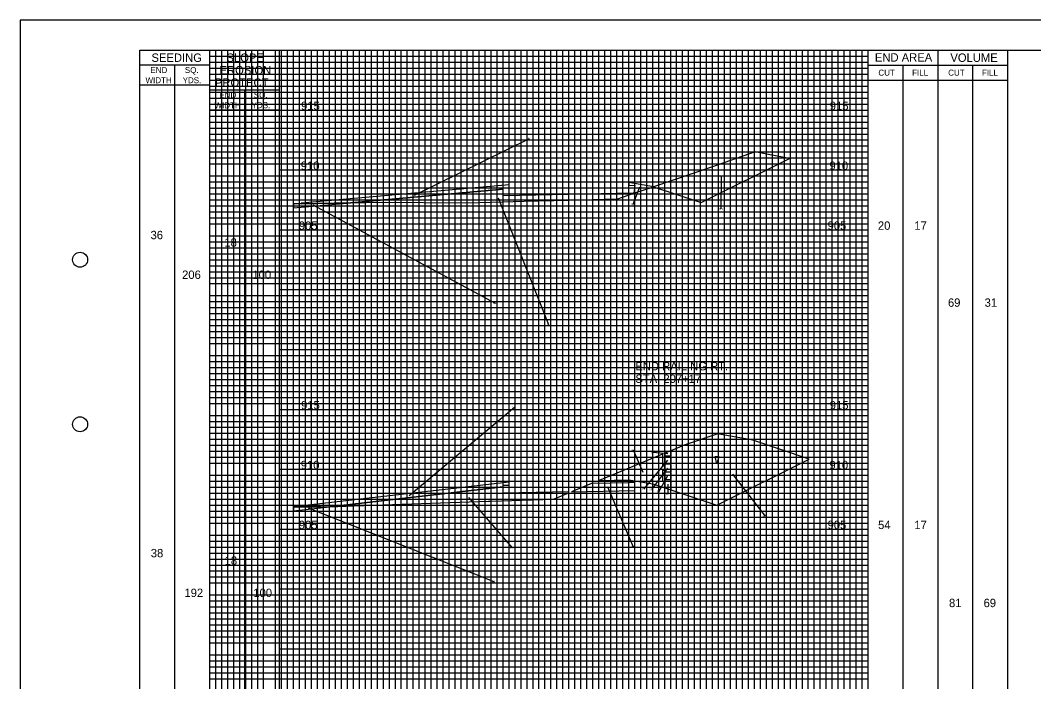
# Model space of a CAD drawing. Extents: x -73 to 160, y -2 to 1877.
# Drawn here: x -10 to 74.7, y 1547.2 to 1602.5 of the extents above; entities that cross this region are included whole.
import ezdxf

# ---------------------------------------------------------------- set-up
doc = ezdxf.new("R2010")
doc.units = 0
for name, color, linetype in [('DR_P_Flood_Boundary', 7, 'Continuous'), ('GK_Cells', 7, 'Continuous'), ('RD_X_Fence', 7, 'Continuous'), ('TX_X_5', 7, 'Continuous'), ('UT_P_Water_Cells', 7, 'Continuous'), ('XS_P_Pavt_Surface', 7, 'Continuous'), ('XS_X_Ground_Line', 7, 'Continuous')]:
    doc.layers.add(name, color=color, linetype=linetype)

msp = doc.modelspace()

# ---------------------------------------------------------------- linework, layer by layer
at = {"layer": 'DR_P_Flood_Boundary'}
for p, q in [((15.832, 1495), (15.832, 1600)), ((20.832, 1495), (20.832, 1600)), ((25.832, 1495), (25.832, 1600)), ((30.832, 1495), (30.832, 1600)), ((35.832, 1495), (35.832, 1600)), ((40.832, 1495), (40.832, 1600)), ((45.832, 1495), (45.832, 1600)), ((50.832, 1495), (50.832, 1600)), ((55.832, 1495), (55.832, 1600)), ((5.832, 1595), (60.832, 1595)), ((11.665, 1590), (60.832, 1590)), ((11.665, 1585), (60.832, 1585)), ((11.665, 1580), (60.832, 1580)), ((11.665, 1575), (60.832, 1575)), ((11.665, 1570), (60.832, 1570)), ((11.665, 1565), (60.832, 1565)), ((11.665, 1560), (60.832, 1560)), ((11.665, 1555), (60.832, 1555)), ((11.665, 1550), (60.832, 1550))]:
    msp.add_line(p, q, dxfattribs=at)
at = {"layer": 'GK_Cells'}
msp.add_lwpolyline([(0, 1600), (157.5, 1600), (157.5, 1495), (0, 1495)], close=True, dxfattribs=at)
for centre in [(-5, 1582.5), (-5, 1568.75)]:
    msp.add_circle(centre, 0.625, dxfattribs=at)
at = {"layer": 'RD_X_Fence'}
for p, q in [((22.926, 1587.9), (32.526, 1592.622)), ((46.887, 1587.271), (54.269, 1590.962)), ((48.543, 1589.429), (48.514, 1586.74)), ((30.832, 1588.756), (13.453, 1587.215)), ((30.332, 1588.382), (17.617, 1587.255)), ((17.617, 1587.255), (30.332, 1588.382)), ((30.332, 1588.496), (30.832, 1588.506)), ((30.332, 1588.382), (30.332, 1588.496)), ((30.332, 1587.83), (30.332, 1588.382)), ((42.903, 1588.6), (40.832, 1588.956)), ((40.832, 1588.706), (41.332, 1588.716)), ((41.734, 1588.547), (41.176, 1587.101)), ((41.332, 1588.716), (41.266, 1588.048)), ((41.266, 1588.048), (42.903, 1588.6)), ((42.903, 1588.6), (46.887, 1587.271)), ((29.915, 1587.67), (34.129, 1577.084)), ((41.266, 1588.048), (30.332, 1587.83)), ((32.089, 1587.379), (35.833, 1587.482)), ((12.832, 1586.83), (17.617, 1587.255)), ((12.832, 1587.16), (12.832, 1586.83)), ((13.456, 1587.174), (17.617, 1587.255)), ((14.428, 1587.082), (29.683, 1578.883)), ((29.332, 1587.304), (32.089, 1587.379)), ((22.482, 1562.804), (31.277, 1570.192)), ((48.199, 1567.936), (45.462, 1567.016)), ((48.254, 1567.954), (48.199, 1567.936)), ((51.194, 1567.436), (48.254, 1567.954)), ((55.903, 1565.853), (51.194, 1567.436)), ((43.66, 1566.269), (38.365, 1564.072)), ((42.046, 1564.719), (41.215, 1566.586)), ((42.046, 1564.719), (41.215, 1566.586)), ((42.046, 1564.719), (41.215, 1566.586)), ((44.108, 1566.282), (42.835, 1566.384)), ((44.108, 1566.282), (42.835, 1566.384)), ((43.666, 1566.109), (43.666, 1566.253)), ((44.332, 1566.548), (43.832, 1566.34)), ((45.462, 1567.016), (44.332, 1566.548)), ((44.332, 1566.114), (44.332, 1566.548)), ((44.332, 1566.548), (44.332, 1566.114)), ((44.08, 1565.76), (42.094, 1563.359)), ((43.666, 1566.107), (43.625, 1566.109)), ((43.666, 1565.437), (43.625, 1565.439)), ((43.625, 1565.439), (43.666, 1565.439)), ((43.666, 1565.439), (43.666, 1566.107)), ((43.666, 1565.253), (43.666, 1565.437)), ((43.832, 1566.107), (44.332, 1566.109)), ((44.332, 1566.067), (43.832, 1566.097)), ((43.832, 1566.097), (43.832, 1565.437)), ((43.832, 1565.437), (44.332, 1565.439)), ((44.332, 1565.397), (43.832, 1565.427)), ((44.332, 1566.062), (44.332, 1565.444)), ((44.332, 1564.784), (44.332, 1565.392)), ((44.332, 1565.392), (44.332, 1564.784)), ((48.197, 1565.463), (48.037, 1566.063)), ((48.359, 1566.063), (48.197, 1565.463)), ((48.197, 1562), (55.903, 1565.853)), ((44.08, 1565.095), (42.718, 1563.31)), ((43.666, 1564.777), (43.625, 1564.779)), ((43.832, 1565.253), (43.666, 1565.253)), ((43.666, 1564.779), (43.666, 1564.923)), ((43.666, 1564.923), (43.832, 1564.923)), ((43.666, 1564.151), (43.666, 1564.777)), ((43.832, 1564.923), (43.832, 1565.253)), ((43.832, 1564.777), (44.332, 1564.779)), ((44.332, 1564.737), (43.832, 1564.767)), ((43.832, 1564.767), (43.832, 1564.151)), ((44.332, 1564.156), (44.332, 1564.732)), ((44.332, 1564.732), (44.332, 1564.156)), ((49.489, 1564.589), (52.234, 1561.085)), ((30.832, 1563.922), (12.832, 1561.855)), ((30.832, 1563.817), (30.832, 1563.922)), ((30.832, 1563.672), (30.832, 1563.817)), ((37.731, 1563.81), (36.043, 1563.109)), ((38.365, 1564.072), (40.832, 1564.122)), ((40.832, 1564.122), (42.832, 1563.788)), ((41.332, 1563.215), (41.332, 1563.882)), ((42.832, 1563.788), (43.832, 1563.455)), ((44.08, 1564.452), (43.333, 1563.134)), ((43.625, 1564.151), (43.666, 1564.151)), ((43.666, 1564.149), (43.625, 1564.151)), ((43.666, 1563.965), (43.666, 1564.149)), ((43.832, 1563.965), (43.666, 1563.965)), ((43.832, 1564.151), (44.332, 1564.151)), ((44.332, 1564.109), (43.832, 1564.139)), ((43.832, 1563.455), (43.832, 1563.965)), ((44.09, 1563.746), (44.084, 1562.91)), ((44.09, 1563.746), (44.084, 1562.91)), ((44.332, 1563.288), (44.332, 1564.104)), ((44.332, 1564.104), (44.332, 1563.288)), ((30.332, 1563.534), (15.831, 1561.87)), ((15.831, 1561.87), (30.332, 1563.534)), ((30.332, 1563.662), (30.832, 1563.672)), ((30.332, 1563.534), (30.332, 1563.662)), ((30.332, 1562.995), (30.332, 1563.534)), ((35.831, 1563.105), (30.332, 1562.995)), ((34.545, 1562.488), (35.832, 1563.022)), ((36.043, 1563.109), (41.332, 1563.215)), ((39.083, 1563.482), (41.204, 1558.511)), ((43.832, 1563.455), (44.332, 1563.288)), ((44.332, 1563.288), (48.197, 1562)), ((27.453, 1562.64), (31.093, 1558.429)), ((29.332, 1562.344), (34.545, 1562.488)), ((15.82, 1561.968), (12.832, 1561.855)), ((12.832, 1561.525), (15.831, 1561.87)), ((12.832, 1561.855), (12.832, 1561.525)), ((14.062, 1561.784), (29.564, 1555.622))]:
    msp.add_line(p, q, dxfattribs=at)
for points in [[(54.269, 1590.962), (52.631, 1591.248), (51.379, 1591.518), (47.755, 1590.234), (42.903, 1588.6)], [(30.832, 1588.506), (30.832, 1588.652), (30.832, 1588.756)], [(40.832, 1588.956), (40.832, 1588.852), (40.832, 1588.706)], [(35.833, 1587.482), (39.919, 1587.595), (41.266, 1588.048)], [(17.617, 1587.255), (13.456, 1587.174), (12.832, 1587.16)], [(13.453, 1587.215), (13.456, 1587.174)], [(17.617, 1587.255), (20.19, 1587.304), (27.19, 1587.245), (29.332, 1587.304)], [(43.666, 1566.253), (43.66, 1566.269)], [(43.832, 1566.34), (43.832, 1566.253), (43.832, 1566.107)], [(43.625, 1566.109), (43.666, 1566.109)], [(43.832, 1565.427), (43.832, 1565.253), (43.832, 1564.923), (43.832, 1564.777)], [(44.332, 1566.109), (44.332, 1566.114)], [(44.332, 1566.062), (44.332, 1566.067)], [(44.332, 1565.439), (44.332, 1565.444), (44.332, 1566.062)], [(44.332, 1565.392), (44.332, 1565.397)], [(48.037, 1566.063), (48.199, 1566.063), (48.359, 1566.063)], [(43.625, 1564.779), (43.666, 1564.779)], [(44.332, 1564.779), (44.332, 1564.784)], [(44.332, 1564.732), (44.332, 1564.737)], [(41.332, 1563.882), (40.832, 1563.872), (37.731, 1563.81)], [(43.832, 1564.139), (43.832, 1563.965), (43.832, 1563.455)], [(44.332, 1564.151), (44.332, 1564.156)], [(44.332, 1564.104), (44.332, 1564.109)], [(35.832, 1563.022), (35.831, 1563.105)], [(15.831, 1561.87), (17.904, 1561.95), (29.122, 1562.338), (29.332, 1562.344)], [(12.832, 1561.855), (14.061, 1561.861), (15.831, 1561.87)], [(15.831, 1561.87), (15.82, 1561.968)]]:
    msp.add_lwpolyline(points, dxfattribs=at)
for centre in [(44.318, 1566.088), (44.318, 1565.418), (44.318, 1564.758), (44.318, 1564.13)]:
    msp.add_arc(centre, 0.03, 299.86589, 60.13411, dxfattribs=at)
at = {"layer": 'TX_X_5'}
msp.add_lwpolyline([(-10, 1492.5), (160, 1492.5), (160, 1602.5), (-10, 1602.5)], close=True, dxfattribs=at)
at = {"layer": 'UT_P_Water_Cells'}
for p, q in [((5.832, 1599.5), (60.832, 1599.5)), ((6.332, 1495), (6.332, 1600)), ((6.832, 1495), (6.832, 1600)), ((7.332, 1495), (7.332, 1600)), ((7.832, 1495), (7.832, 1600)), ((8.332, 1495), (8.332, 1600)), ((8.832, 1495), (8.832, 1600)), ((9.332, 1495), (9.332, 1600)), ((9.832, 1495), (9.832, 1600)), ((10.332, 1495), (10.332, 1600)), ((11.332, 1495), (11.332, 1600)), ((11.832, 1495), (11.832, 1600)), ((12.332, 1495), (12.332, 1600)), ((12.832, 1495), (12.832, 1600)), ((13.332, 1495), (13.332, 1600)), ((13.832, 1495), (13.832, 1600)), ((14.332, 1495), (14.332, 1600)), ((14.832, 1495), (14.832, 1600)), ((15.332, 1495), (15.332, 1600)), ((16.332, 1495), (16.332, 1600)), ((16.832, 1495), (16.832, 1600)), ((17.332, 1495), (17.332, 1600)), ((17.832, 1495), (17.832, 1600)), ((18.332, 1495), (18.332, 1600)), ((18.832, 1495), (18.832, 1600)), ((19.332, 1495), (19.332, 1600)), ((19.832, 1495), (19.832, 1600)), ((20.332, 1495), (20.332, 1600)), ((21.332, 1495), (21.332, 1600)), ((21.832, 1495), (21.832, 1600)), ((22.332, 1495), (22.332, 1600)), ((22.832, 1495), (22.832, 1600)), ((23.332, 1495), (23.332, 1600)), ((23.832, 1495), (23.832, 1600)), ((24.332, 1495), (24.332, 1600)), ((24.832, 1495), (24.832, 1600)), ((25.332, 1495), (25.332, 1600)), ((26.332, 1495), (26.332, 1600)), ((26.832, 1495), (26.832, 1600)), ((27.332, 1495), (27.332, 1600)), ((27.832, 1495), (27.832, 1600)), ((28.332, 1495), (28.332, 1600)), ((28.832, 1495), (28.832, 1600)), ((29.332, 1495), (29.332, 1600)), ((29.832, 1495), (29.832, 1600)), ((30.332, 1495), (30.332, 1600)), ((31.332, 1495), (31.332, 1600)), ((31.832, 1495), (31.832, 1600)), ((32.332, 1495), (32.332, 1600)), ((32.832, 1495), (32.832, 1600)), ((33.332, 1495), (33.332, 1600)), ((33.832, 1495), (33.832, 1600)), ((34.332, 1495), (34.332, 1600)), ((34.832, 1495), (34.832, 1600)), ((35.332, 1495), (35.332, 1600)), ((36.332, 1495), (36.332, 1600)), ((36.832, 1495), (36.832, 1600)), ((37.332, 1495), (37.332, 1600)), ((37.832, 1495), (37.832, 1600)), ((38.332, 1495), (38.332, 1600)), ((38.832, 1495), (38.832, 1600)), ((39.332, 1495), (39.332, 1600)), ((39.832, 1495), (39.832, 1600)), ((40.332, 1495), (40.332, 1600)), ((41.332, 1495), (41.332, 1600)), ((41.832, 1495), (41.832, 1600)), ((42.332, 1495), (42.332, 1600)), ((42.832, 1495), (42.832, 1600)), ((43.332, 1495), (43.332, 1600)), ((43.832, 1495), (43.832, 1600)), ((44.332, 1495), (44.332, 1600)), ((44.832, 1495), (44.832, 1600)), ((45.332, 1495), (45.332, 1600)), ((46.332, 1495), (46.332, 1600)), ((46.832, 1495), (46.832, 1600)), ((47.332, 1495), (47.332, 1600)), ((47.832, 1495), (47.832, 1600)), ((48.332, 1495), (48.332, 1600)), ((48.832, 1495), (48.832, 1600)), ((49.332, 1495), (49.332, 1600)), ((49.832, 1495), (49.832, 1600)), ((50.332, 1495), (50.332, 1600)), ((51.332, 1495), (51.332, 1600)), ((51.832, 1495), (51.832, 1600)), ((52.332, 1495), (52.332, 1600)), ((52.832, 1495), (52.832, 1600)), ((53.332, 1495), (53.332, 1600)), ((53.832, 1495), (53.832, 1600)), ((54.332, 1495), (54.332, 1600)), ((54.832, 1495), (54.832, 1600)), ((55.332, 1495), (55.332, 1600)), ((56.332, 1495), (56.332, 1600)), ((56.832, 1495), (56.832, 1600)), ((57.332, 1495), (57.332, 1600)), ((57.832, 1495), (57.832, 1600)), ((58.332, 1495), (58.332, 1600)), ((58.832, 1495), (58.832, 1600)), ((59.332, 1495), (59.332, 1600)), ((59.832, 1495), (59.832, 1600)), ((60.332, 1495), (60.332, 1600)), ((5.832, 1599), (60.832, 1599)), ((5.832, 1598.5), (60.832, 1598.5)), ((5.832, 1598), (60.832, 1598)), ((5.832, 1597.5), (60.832, 1597.5)), ((5.832, 1597), (60.832, 1597)), ((5.832, 1596.5), (60.832, 1596.5)), ((5.832, 1596), (60.832, 1596)), ((5.832, 1595.5), (60.832, 1595.5)), ((5.832, 1594.5), (60.832, 1594.5)), ((5.832, 1594), (60.832, 1594)), ((5.832, 1593.5), (60.832, 1593.5)), ((5.832, 1593), (60.832, 1593)), ((5.832, 1592.5), (60.832, 1592.5)), ((5.832, 1592), (60.832, 1592)), ((5.832, 1591.5), (60.832, 1591.5)), ((5.832, 1591), (60.832, 1591)), ((5.832, 1590.5), (60.832, 1590.5)), ((5.832, 1589.5), (60.832, 1589.5)), ((5.832, 1589), (60.832, 1589)), ((5.832, 1588.5), (60.832, 1588.5)), ((5.832, 1588), (60.832, 1588)), ((5.832, 1587.5), (60.832, 1587.5)), ((5.832, 1587), (60.832, 1587)), ((5.832, 1586.5), (60.832, 1586.5)), ((5.832, 1586), (60.832, 1586)), ((5.832, 1585.5), (60.832, 1585.5)), ((5.832, 1584.5), (60.832, 1584.5)), ((5.832, 1584), (60.832, 1584)), ((5.832, 1583.5), (60.832, 1583.5)), ((5.832, 1583), (60.832, 1583)), ((5.832, 1582.5), (60.832, 1582.5)), ((5.832, 1582), (60.832, 1582)), ((5.832, 1581.5), (60.832, 1581.5)), ((5.832, 1581), (60.832, 1581)), ((5.832, 1580.5), (60.832, 1580.5)), ((5.832, 1579.5), (60.832, 1579.5)), ((5.832, 1579), (60.832, 1579)), ((5.832, 1578.5), (60.832, 1578.5)), ((5.832, 1578), (60.832, 1578)), ((5.832, 1577.5), (60.832, 1577.5)), ((5.832, 1577), (60.832, 1577)), ((5.832, 1576.5), (60.832, 1576.5)), ((5.832, 1576), (60.832, 1576)), ((5.832, 1575.5), (60.832, 1575.5)), ((5.832, 1574.5), (60.832, 1574.5)), ((5.832, 1574), (60.832, 1574)), ((5.832, 1573.5), (60.832, 1573.5)), ((5.832, 1573), (60.832, 1573)), ((5.832, 1572.5), (60.832, 1572.5)), ((5.832, 1572), (60.832, 1572)), ((5.832, 1571.5), (60.832, 1571.5)), ((5.832, 1571), (60.832, 1571)), ((5.832, 1570.5), (60.832, 1570.5)), ((5.832, 1569.5), (60.832, 1569.5)), ((5.832, 1569), (60.832, 1569)), ((5.832, 1568.5), (60.832, 1568.5)), ((5.832, 1568), (60.832, 1568)), ((5.832, 1567.5), (60.832, 1567.5)), ((5.832, 1567), (60.832, 1567)), ((5.832, 1566.5), (60.832, 1566.5)), ((5.832, 1566), (60.832, 1566)), ((5.832, 1565.5), (60.832, 1565.5)), ((5.832, 1564.5), (60.832, 1564.5)), ((5.832, 1564), (60.832, 1564)), ((5.832, 1563.5), (60.832, 1563.5)), ((5.832, 1563), (60.832, 1563)), ((5.832, 1562.5), (60.832, 1562.5)), ((5.832, 1562), (60.832, 1562)), ((5.832, 1561.5), (60.832, 1561.5)), ((5.832, 1561), (60.832, 1561)), ((5.832, 1560.5), (60.832, 1560.5)), ((5.832, 1559.5), (60.832, 1559.5)), ((5.832, 1559), (60.832, 1559)), ((5.832, 1558.5), (60.832, 1558.5)), ((5.832, 1558), (60.832, 1558)), ((5.832, 1557.5), (60.832, 1557.5)), ((5.832, 1557), (60.832, 1557)), ((5.832, 1556.5), (60.832, 1556.5)), ((5.832, 1556), (60.832, 1556)), ((5.832, 1555.5), (60.832, 1555.5)), ((5.832, 1554.5), (60.832, 1554.5)), ((5.832, 1554), (60.832, 1554)), ((5.832, 1553.5), (60.832, 1553.5)), ((5.832, 1553), (60.832, 1553)), ((5.832, 1552.5), (60.832, 1552.5)), ((5.832, 1552), (60.832, 1552)), ((5.832, 1551.5), (60.832, 1551.5)), ((5.832, 1551), (60.832, 1551)), ((5.832, 1550.5), (60.832, 1550.5)), ((5.832, 1549.5), (60.832, 1549.5)), ((5.832, 1549), (60.832, 1549)), ((5.832, 1548.5), (60.832, 1548.5)), ((5.832, 1548), (60.832, 1548)), ((5.832, 1547.5), (60.832, 1547.5))]:
    msp.add_line(p, q, dxfattribs=at)
at = {"layer": 'XS_X_Ground_Line'}
for p, q in [((5.832, 1495), (5.832, 1600)), ((5.832, 1495), (5.832, 1600)), ((11.665, 1495), (11.665, 1600)), ((60.832, 1495), (60.832, 1600)), ((66.667, 1495), (66.667, 1600)), ((72.5, 1495), (72.5, 1600)), ((5.832, 1598.75), (0, 1598.75)), ((2.916, 1495), (2.916, 1598.75)), ((60.832, 1598.75), (72.5, 1598.75)), ((63.75, 1495), (63.75, 1598.75)), ((69.583, 1495), (69.583, 1598.75)), ((5.832, 1597.083), (0, 1597.083)), ((60.832, 1597.5), (72.5, 1597.5)), ((11.665, 1596.667), (5.832, 1596.667)), ((8.749, 1495), (8.749, 1596.667)), ((11.665, 1595), (5.832, 1595))]:
    msp.add_line(p, q, dxfattribs=at)

# ---------------------------------------------------------------- texts
at = {"layer": 'RD_X_Fence'}
for s, p in [('5.1', (32.391, 1592.552)), ('0.8', (41.023, 1587.031)), ('18.6', (48.33, 1586.67)), ('0.8', (29.52, 1578.813)), ('11.6', (33.964, 1577.014)), ('5.4', (31.119, 1570.122)), ('6.5', (41.068, 1566.516)), ('0.2', (42.683, 1566.314)), ('0.3', (41.941, 1563.289)), ('0.3', (42.565, 1563.24)), ('0.3', (43.18, 1563.064)), ('0.4', (43.932, 1562.84)), ('42.0', (52.022, 1561.015)), ('11.3', (30.928, 1558.359)), ('3.0', (41.042, 1558.441)), ('0.6', (29.398, 1555.552))]:
    msp.add_text(s, height=0.14, dxfattribs=at).set_placement(p)
at = {"layer": 'XS_P_Pavt_Surface'}
for s, p in [('915', (13.458, 1595)), ('915', (57.625, 1595)), ('910', (13.43, 1590)), ('910', (57.598, 1590)), ('905', (13.27, 1585)), ('905', (57.438, 1585)), ('20', (61.644, 1585)), ('36', (0.885, 1584.212)), ('17', (64.689, 1585)), ('18', (7.052, 1583.593)), ('206', (3.519, 1580.895)), ('100', (9.394, 1580.895)), ('69', (67.496, 1578.569)), ('31', (70.557, 1578.569)), ('END RAILING RT.', (41.385, 1573.257)), ('STA. 207+17', (41.385, 1572.207)), ('915', (13.458, 1570)), ('915', (57.625, 1570)), ('910', (13.43, 1565)), ('910', (57.598, 1565)), ('905', (13.27, 1560)), ('905', (57.438, 1560)), ('54', (61.66, 1560)), ('17', (64.689, 1560)), ('38', (0.904, 1557.641)), ('18', (7.074, 1557.021)), ('192', (3.713, 1554.324)), ('100', (9.468, 1554.324)), ('81', (67.587, 1553.481)), ('69', (70.472, 1553.481))]:
    msp.add_text(s, height=0.7, dxfattribs=at).set_placement(p)
at = {"layer": 'XS_X_Ground_Line'}
for s, height, p in [('SEEDING', 0.7, (0.964, 1599.025)), ('SLOPE', 0.7, (7.228, 1599.025)), ('END AREA', 0.7, (61.394, 1599.047)), ('VOLUME', 0.7, (67.698, 1599.025)), ('END', 0.5, (0.87, 1598.092)), ('SQ.', 0.5, (3.748, 1598.092)), ('EROSION', 0.7, (6.649, 1597.983)), ('WIDTH', 0.5, (0.462, 1597.242)), ('YDS.', 0.5, (3.563, 1597.242)), ('PROTECT.', 0.7, (6.26, 1596.942)), ('CUT', 0.5, (61.683, 1597.875)), ('FILL', 0.5, (64.502, 1597.875)), ('CUT', 0.5, (67.517, 1597.875)), ('FILL', 0.5, (70.335, 1597.875)), ('END', 0.5, (6.631, 1596.008)), ('SQ.', 0.5, (9.51, 1596.008)), ('WIDTH', 0.5, (6.224, 1595.158)), ('YDS.', 0.5, (9.325, 1595.158))]:
    msp.add_text(s, height=height, dxfattribs=at).set_placement(p)

doc.saveas('drawing.dxf')
